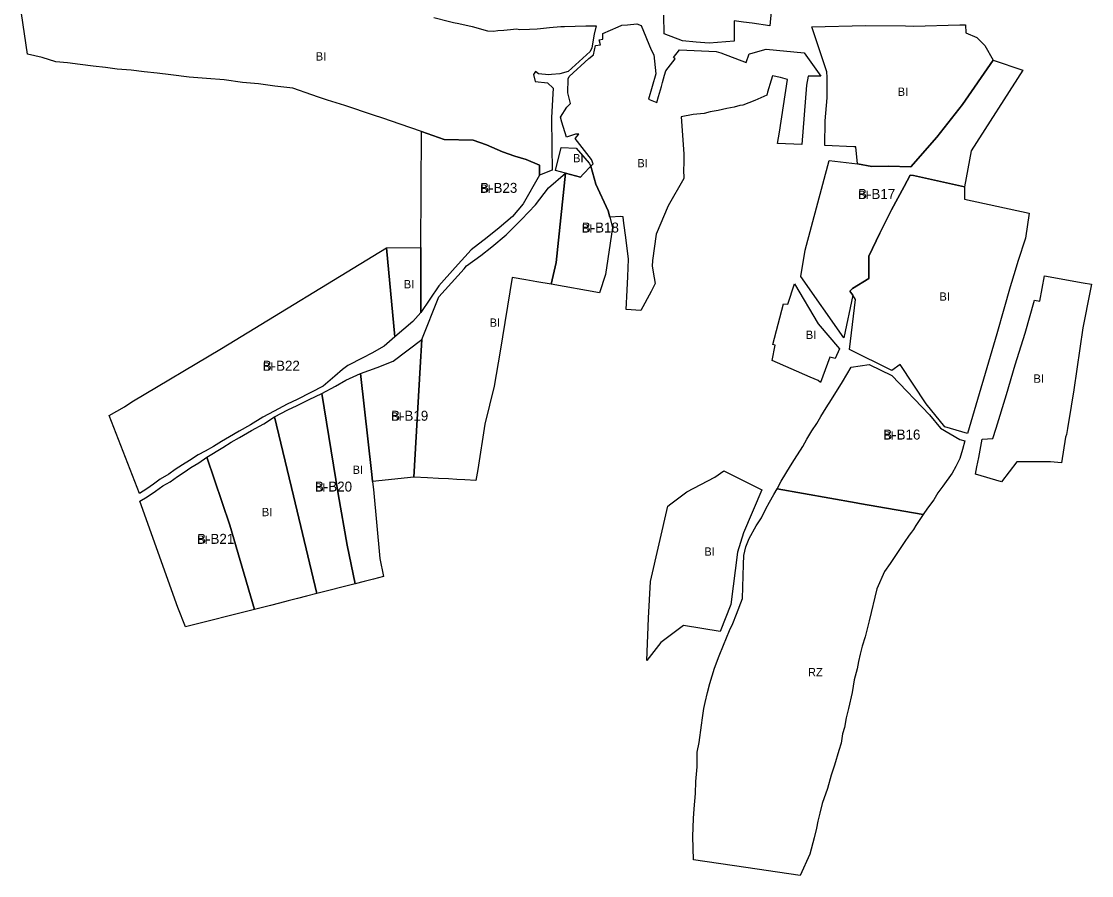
# Model space of a CAD drawing. Extents: x -532081 to -530154, y -1179372 to -1177675.
# Drawn here: x -531490 to -530847, y -1178963 to -1178449 of the extents above; entities that cross this region are included whole.
import ezdxf

# ---------------------------------------------------------------- set-up
doc = ezdxf.new("R2010")
doc.units = 0
for name, color, linetype in [('90040013', 7, 'Continuous'), ('90040023', 7, 'Continuous'), ('90100013', 7, 'Continuous'), ('ID_navrh', 7, 'Continuous')]:
    doc.layers.add(name, color=color, linetype=linetype)

msp = doc.modelspace()

# ---------------------------------------------------------------- linework, layer by layer
at = {"layer": '90040013'}
for points in [[(-531038.59, -1178437.02), (-531040.03, -1178451.99), (-531050.64, -1178450.37), (-531055.86, -1178449.83), (-531061.44, -1178449.1), (-531061.44, -1178461.19), (-531076.38, -1178462.4), (-531084.22, -1178461.79), (-531092.53, -1178461.07), (-531103.5, -1178456.96), (-531103.74, -1178445.71)], [(-531241.84, -1178446.98), (-531232.53, -1178449.47), (-531230.18, -1178450.1), (-531226.87, -1178450.69), (-531218.89, -1178452.44), (-531209.75, -1178454.98), (-531206.06, -1178455.37), (-531203.48, -1178454.81), (-531199.75, -1178454.64), (-531195.9, -1178454.24), (-531192.27, -1178453.8), (-531190.29, -1178454.35), (-531184.34, -1178454.13), (-531179.83, -1178453.91), (-531177.85, -1178453.72), (-531172.39, -1178453.06), (-531165.63, -1178452.5), (-531163.38, -1178452.4), (-531150.57, -1178452.02), (-531144.29, -1178452.15), (-531145.55, -1178457.17), (-531146.98, -1178465.31), (-531147.93, -1178467.42), (-531161.25, -1178479.55), (-531166.29, -1178480.88), (-531171.17, -1178481.25), (-531172.83, -1178481.5), (-531179.04, -1178480.9), (-531180.76, -1178479.53), (-531181.97, -1178481.41), (-531180.96, -1178485.59), (-531173.52, -1178486.27), (-531170.25, -1178489.55), (-531170.48, -1178492.94), (-531171.13, -1178507.09), (-531170.94, -1178524.81), (-531170.78, -1178538.85), (-531178.46, -1178541.91), (-531178.31, -1178535.78), (-531186.51, -1178532.36), (-531193.32, -1178530.34), (-531200.6, -1178527.7), (-531210.2, -1178523.66), (-531218.27, -1178520.75), (-531235.78, -1178520.31), (-531249.37, -1178515.57), (-531262.22, -1178511.21), (-531272.6, -1178507.61), (-531278.25, -1178505.73), (-531295.36, -1178500.01), (-531305.79, -1178496.65), (-531311.3, -1178494.88), (-531315.23, -1178493.5), (-531326.64, -1178489.55), (-531337.48, -1178488.37), (-531347.31, -1178486.98), (-531356.95, -1178486.2), (-531367.96, -1178484.62), (-531378.59, -1178483.63), (-531389.01, -1178482.84), (-531400.03, -1178481.46), (-531408.09, -1178480.47), (-531415.96, -1178479.68), (-531423.82, -1178478.7), (-531432.09, -1178478.11), (-531439.17, -1178477.12), (-531446.64, -1178476.33), (-531454.51, -1178475.34), (-531461.98, -1178474.36), (-531469.06, -1178473.77), (-531477.33, -1178471.2), (-531486.01, -1178469.03), (-531489.73, -1178444.75)]]:
    msp.add_lwpolyline(points, dxfattribs=at)
for points in [[(-531147.65, -1178536.43), (-531146.23, -1178534.97), (-531147.19, -1178532.46), (-531156.94, -1178519.71), (-531154.83, -1178517.16), (-531156.76, -1178517.26), (-531162.17, -1178518.99), (-531165.08, -1178509.9), (-531165.86, -1178506.92), (-531161.98, -1178500.97), (-531159.76, -1178498.66), (-531161.34, -1178492.33), (-531161.12, -1178483.96), (-531160.67, -1178482.6), (-531148.72, -1178471.75), (-531146.01, -1178469.49), (-531144.66, -1178463.84), (-531141.79, -1178463.58), (-531142.5, -1178460.54), (-531140.31, -1178460.04), (-531140.38, -1178456.6), (-531131.13, -1178452.75), (-531128.88, -1178451.62), (-531125.5, -1178451.4), (-531119.86, -1178450.95), (-531117.38, -1178451.85), (-531111.3, -1178466.55), (-531109.78, -1178469.48), (-531108.48, -1178480.88), (-531112.99, -1178496.17), (-531107.96, -1178498.18), (-531106.89, -1178494.51), (-531105.15, -1178488.56), (-531104.53, -1178486.14), (-531103.35, -1178481.73), (-531102.59, -1178479.09), (-531096.89, -1178471.98), (-531097.93, -1178471.15), (-531094.21, -1178466.52), (-531072.17, -1178467.44), (-531069.49, -1178468.26), (-531054.18, -1178474.07), (-531052.38, -1178468.88), (-531051.45, -1178468.62), (-531042.3, -1178466.11), (-531019.42, -1178468.38), (-531009.35, -1178482.35), (-531016.9, -1178482.35), (-531017.93, -1178487.67), (-531020.87, -1178523.48), (-531035.3, -1178522.85), (-531034.28, -1178516.02), (-531029.48, -1178484.28), (-531033.57, -1178483.21), (-531038.37, -1178482.14), (-531039.26, -1178484.64), (-531041.39, -1178491.95), (-531041.75, -1178493.73), (-531049.11, -1178497), (-531056.22, -1178499.75), (-531058.03, -1178499.97), (-531061.42, -1178500.88), (-531065.94, -1178501.79), (-531071.14, -1178502.92), (-531075.89, -1178503.83), (-531079.51, -1178504.74), (-531086.1, -1178505.3), (-531093.28, -1178506.82), (-531091.61, -1178529.05), (-531091.65, -1178534.79), (-531091.86, -1178538.38), (-531091.72, -1178543.75), (-531101, -1178560.31), (-531108.31, -1178577.24), (-531110.57, -1178593.08), (-531110.69, -1178596.42), (-531109.5, -1178603.44), (-531108.91, -1178606.9), (-531111.4, -1178611.78), (-531117.46, -1178623.21), (-531126.26, -1178622.6), (-531125.77, -1178610.94), (-531125.29, -1178602.61), (-531124.94, -1178592.25), (-531126.39, -1178580.96), (-531128, -1178569.06), (-531128.14, -1178566.76), (-531129.57, -1178566.64), (-531136.08, -1178567.01), (-531137.19, -1178563.31), (-531144.46, -1178547.24)], [(-530922.36, -1178451.42), (-530922.24, -1178456.29), (-530915.72, -1178459.01), (-530910.89, -1178463.79), (-530905.76, -1178472.63), (-530924.32, -1178499.4), (-530939.6, -1178518.98), (-530955.29, -1178536.9), (-530968.7, -1178536.38), (-530978.65, -1178536.57), (-530987.3, -1178534.98), (-530988.4, -1178524.84), (-530989.44, -1178524.84), (-531006.92, -1178524.08), (-531006.76, -1178509.16), (-531005.65, -1178495.35), (-531005.49, -1178482.97), (-531005.81, -1178479.79), (-531013.6, -1178456.32), (-531014.8, -1178452.7), (-530982.48, -1178451.8), (-530958.48, -1178452.03), (-530953.63, -1178452.19), (-530925.9, -1178451.51)], [(-531147.65, -1178536.43), (-531152.22, -1178541.12), (-531153.85, -1178542.92), (-531162.87, -1178540.69), (-531168.71, -1178539.1), (-531165.45, -1178525.23), (-531156.32, -1178525.58), (-531148.57, -1178534.56)], [(-531162.87, -1178540.69), (-531168.4, -1178594.27), (-531171.41, -1178607.36), (-531179.93, -1178605.87), (-531186.56, -1178604.71), (-531194.79, -1178603.27), (-531201.96, -1178647.61), (-531205.61, -1178668.57), (-531211.19, -1178691.48), (-531215.41, -1178718.6), (-531216.62, -1178725.33), (-531223.2, -1178724.95), (-531228.01, -1178724.68), (-531233.15, -1178724.39), (-531239.08, -1178724.05), (-531245.8, -1178723.67), (-531253.89, -1178723.21), (-531250.15, -1178657.42), (-531249.19, -1178640.53), (-531238.8, -1178614.88), (-531223.64, -1178598.1), (-531222.18, -1178596.27), (-531213.65, -1178590.04), (-531207.08, -1178584.91), (-531198.43, -1178577.58), (-531189.17, -1178568.54), (-531180.77, -1178559.74), (-531172.98, -1178549.48)], [(-530903.62, -1178637.17), (-530921.15, -1178697.01), (-530934.83, -1178693.04), (-530946.16, -1178679.14), (-530961.63, -1178655.5), (-530966.67, -1178659.29), (-530992.04, -1178646.66), (-530988.44, -1178616.52), (-530990.22, -1178613.95), (-530991.89, -1178611.53), (-530990.36, -1178610), (-530980.53, -1178603.86), (-530980.53, -1178590.49), (-530973.97, -1178576.69), (-530966.98, -1178562.66), (-530959.33, -1178548.63), (-530955.62, -1178541.84), (-530953.65, -1178542.06), (-530923.06, -1178548.85), (-530923.06, -1178556.3), (-530884.17, -1178564.63), (-530886.36, -1178579.75), (-530890.95, -1178593.78), (-530892.57, -1178599.13), (-530895.53, -1178608.9), (-530899.47, -1178622.27)], [(-531254.57, -1178629.67), (-531265.42, -1178638.9), (-531270.28, -1178585.45), (-531249.65, -1178585.37), (-531249.81, -1178624.39)], [(-530847.45, -1178611.31), (-530851.93, -1178633.6), (-530857.36, -1178670.82), (-530858.98, -1178680.59), (-530861.22, -1178694.07), (-530861.82, -1178697.62), (-530862.27, -1178699.3), (-530864.65, -1178714.67), (-530871.39, -1178714.02), (-530891.58, -1178714.02), (-530900.79, -1178726.01), (-530916.47, -1178721.44), (-530915.6, -1178717.02), (-530914.51, -1178711.45), (-530912.36, -1178700.52), (-530905.95, -1178699.97), (-530904.06, -1178693.87), (-530897.78, -1178673.68), (-530892.49, -1178655.71), (-530886.59, -1178636.78), (-530880.93, -1178616.84), (-530877.85, -1178617.45), (-530874.9, -1178602.31), (-530851.63, -1178606.49), (-530846.66, -1178607.39)], [(-531025.14, -1178607.14), (-531010.93, -1178631.14), (-530998.16, -1178646.12), (-531000.68, -1178651.89), (-531003.91, -1178651.17), (-531009.49, -1178666.33), (-531010.9, -1178665.28), (-531015.7, -1178663.11), (-531038.64, -1178653.15), (-531036.84, -1178643.95), (-531038.28, -1178643.59), (-531031.8, -1178619.23), (-531029.1, -1178619.41)], [(-531283.71, -1178786.01), (-531289.09, -1178787.37), (-531293.9, -1178764.23), (-531299.3, -1178733.22), (-531309.26, -1178673), (-531300.96, -1178668.53), (-531294.88, -1178664.96), (-531285.94, -1178660.96), (-531279.19, -1178721.77), (-531278.72, -1178725.97), (-531278.35, -1178729.31), (-531278.19, -1178730.75), (-531274.27, -1178772.11), (-531272.15, -1178783.07), (-531278.06, -1178784.57)], [(-531340.07, -1178800.34), (-531349.62, -1178802.77), (-531364.57, -1178752.17), (-531378.23, -1178711.23), (-531368.59, -1178705.43), (-531363.69, -1178702.3), (-531358.65, -1178699.48), (-531351.53, -1178695.16), (-531343.97, -1178691.15), (-531337.59, -1178687.13), (-531326.29, -1178734.45), (-531312.3, -1178793.28), (-531318.39, -1178794.83), (-531323.86, -1178796.22), (-531329.37, -1178797.62), (-531334.63, -1178798.96)], [(-531063.52, -1178799.91), (-531069.76, -1178816.05), (-531091.95, -1178812.38), (-531105.52, -1178822.64), (-531113.89, -1178833.52), (-531112.99, -1178807.99), (-531111.8, -1178786.05), (-531101.21, -1178740.77), (-531099.47, -1178739.37), (-531089.95, -1178732.07), (-531073.08, -1178723.27), (-531067.67, -1178719.52), (-531044.85, -1178730.85), (-531055.85, -1178756.7), (-531059.52, -1178768.34)]]:
    msp.add_lwpolyline(points, close=True, dxfattribs=at)
at = {"layer": '90040023'}
for points in [[(-530923.06, -1178548.85), (-530953.65, -1178542.06), (-530955.62, -1178541.84), (-530959.33, -1178548.63), (-530966.98, -1178562.66), (-530973.97, -1178576.69), (-530980.53, -1178590.49), (-530980.53, -1178603.86), (-530990.36, -1178610), (-530991.89, -1178611.53), (-530990.22, -1178613.95), (-530995.62, -1178639.62), (-531021.29, -1178602.76), (-531018.78, -1178586.88), (-531004.28, -1178532.99), (-530987.3, -1178534.98), (-530978.65, -1178536.57), (-530968.7, -1178536.38), (-530955.29, -1178536.9), (-530939.6, -1178518.98), (-530924.32, -1178499.4), (-530905.76, -1178472.63), (-530888.03, -1178478.75), (-530919.11, -1178527.18)], [(-531249.65, -1178585.37), (-531249.37, -1178515.57), (-531235.78, -1178520.31), (-531218.27, -1178520.75), (-531210.2, -1178523.66), (-531200.6, -1178527.7), (-531193.32, -1178530.34), (-531186.51, -1178532.36), (-531178.31, -1178535.78), (-531178.46, -1178541.91), (-531188.2, -1178559.01), (-531194.65, -1178566.58), (-531202.57, -1178573.55), (-531209.88, -1178579.29), (-531219.38, -1178586.77), (-531229.13, -1178597.22), (-531238.88, -1178608.34), (-531249.81, -1178624.39)], [(-531168.4, -1178594.27), (-531162.87, -1178540.69), (-531153.85, -1178542.92), (-531152.22, -1178541.12), (-531147.65, -1178536.43), (-531144.46, -1178547.24), (-531137.19, -1178563.31), (-531136.08, -1178567.01), (-531134.6, -1178573.31), (-531138.67, -1178601.49), (-531142.43, -1178612.44), (-531171.41, -1178607.36)], [(-531437.02, -1178686.21), (-531427.79, -1178681.11), (-531423.31, -1178678.05), (-531369.55, -1178646.03), (-531270.28, -1178585.45), (-531265.42, -1178638.9), (-531271.67, -1178644.51), (-531279.23, -1178648.79), (-531284.65, -1178651.59), (-531293.53, -1178656.21), (-531296.81, -1178658.68), (-531301.42, -1178662.64), (-531308.44, -1178668.53), (-531315.87, -1178672.48), (-531323.98, -1178676.66), (-531330.06, -1178679.48), (-531337.93, -1178683.66), (-531344.69, -1178687.27), (-531352, -1178691.78), (-531358.87, -1178695.62), (-531364.61, -1178699.01), (-531369.51, -1178701.85), (-531374.3, -1178704.82), (-531379.22, -1178707.64), (-531383.44, -1178709.9), (-531388.65, -1178713.28), (-531393.01, -1178715.96), (-531397.37, -1178718.64), (-531401.16, -1178721.47), (-531406.37, -1178724.43), (-531410.45, -1178727.53), (-531414.39, -1178730.36), (-531418.75, -1178733.18)], [(-531253.89, -1178723.21), (-531278.72, -1178725.97), (-531279.19, -1178721.77), (-531285.94, -1178660.96), (-531275.96, -1178657.36), (-531266.37, -1178653.55), (-531249.19, -1178640.53), (-531250.15, -1178657.42)], [(-530988.05, -1178738.71), (-531035.66, -1178730.29), (-531033.11, -1178725.68), (-531030.47, -1178721.06), (-531027.63, -1178716.45), (-531025.13, -1178712.69), (-531020.21, -1178704.79), (-531017.85, -1178700.45), (-531014.7, -1178695.52), (-531011.75, -1178690.98), (-531009.39, -1178686.83), (-531006.14, -1178681.7), (-531002.9, -1178676.57), (-530996.32, -1178665.91), (-530991.21, -1178657.23), (-530980.39, -1178655.65), (-530966.61, -1178662.16), (-530943.99, -1178685.84), (-530937.49, -1178693.94), (-530925.88, -1178700.65), (-530922.86, -1178701.47), (-530924.3, -1178706.59), (-530925.89, -1178712.02), (-530928.28, -1178716.98), (-530930.51, -1178720.98), (-530936.13, -1178728.8), (-530938.97, -1178732.79), (-530941.53, -1178736.92), (-530945.22, -1178741.9), (-530947.92, -1178745.75), (-530986.1, -1178739.05)], [(-531312.3, -1178793.28), (-531326.29, -1178734.45), (-531337.59, -1178687.13), (-531329.73, -1178682.81), (-531324.1, -1178680.14), (-531316.83, -1178676.72), (-531309.26, -1178673), (-531299.3, -1178733.22), (-531293.9, -1178764.23), (-531289.09, -1178787.37)], [(-531395.73, -1178801.65), (-531418.64, -1178737.77), (-531414.06, -1178735.09), (-531409.1, -1178731.64), (-531404.71, -1178728.58), (-531400.32, -1178726.09), (-531395.93, -1178722.83), (-531391.92, -1178720.35), (-531387.91, -1178717.47), (-531383.14, -1178714.6), (-531378.23, -1178711.23), (-531364.57, -1178752.17), (-531349.62, -1178802.77), (-531391.16, -1178813.33)]]:
    msp.add_lwpolyline(points, close=True, dxfattribs=at)
at = {"layer": '90100013'}
msp.add_lwpolyline([(-531085.02, -1178917.99), (-531084.62, -1178913.33), (-531084.45, -1178906.18), (-531083.75, -1178897.46), (-531083.58, -1178888.57), (-531082.4, -1178882.8), (-531081, -1178872.25), (-531080.44, -1178867.9), (-531079.6, -1178862.41), (-531078.9, -1178858.76), (-531077.48, -1178852.78), (-531076.04, -1178847.33), (-531073.32, -1178838.03), (-531070.5, -1178830.75), (-531067.88, -1178824.35), (-531066.06, -1178819.77), (-531064.23, -1178815.45), (-531062.27, -1178811.25), (-531060.05, -1178805.62), (-531056.39, -1178796.19), (-531055.87, -1178775.77), (-531055.61, -1178770.4), (-531054.35, -1178765.15), (-531052.4, -1178760.14), (-531048.19, -1178752.58), (-531045.05, -1178747.67), (-531042.31, -1178742.37), (-531040.26, -1178738.25), (-531037.61, -1178733.63), (-531035.66, -1178730.29), (-530988.05, -1178738.71), (-530986.1, -1178739.05), (-530947.92, -1178745.75), (-530950.75, -1178749.88), (-530952.25, -1178752.26), (-530953.75, -1178754.65), (-530954.98, -1178756.41), (-530956.21, -1178758.17), (-530959.26, -1178762.52), (-530962.54, -1178767.34), (-530967.68, -1178775.28), (-530971.01, -1178779.99), (-530975.71, -1178790.32), (-530980.25, -1178809.61), (-530982.82, -1178819.34), (-530984.55, -1178824.85), (-530985.68, -1178829.73), (-530986.7, -1178834.04), (-530987.61, -1178838.58), (-530989.3, -1178845.04), (-530990.51, -1178852.78), (-530992.75, -1178862.4), (-530994.19, -1178867.86), (-530995.08, -1178873.66), (-530996.34, -1178877.46), (-530997.18, -1178883.08), (-530998.58, -1178887.58), (-531001.24, -1178896.3), (-531003.09, -1178902.34), (-531005.35, -1178910.36), (-531008.65, -1178919.43), (-531010.04, -1178925.19), (-531011.24, -1178930.01), (-531012.03, -1178934.27), (-531013.45, -1178939.97), (-531015.97, -1178949.93), (-531021.8, -1178962.74), (-531028.52, -1178961.73), (-531054.44, -1178957.84), (-531085.97, -1178953.25), (-531086.28, -1178939.33), (-531085.81, -1178928.42), (-531085.49, -1178922.57)], close=True, dxfattribs=at)

# ---------------------------------------------------------------- texts
at = {"layer": '90040013'}
for rotation, p in [(0, (-531312.86, -1178472.94)), (360, (-530963.16, -1178494.16)), (0, (-531158.26, -1178534.08)), (0, (-531119.62, -1178537.08)), (0, (-531259.97, -1178609.83)), (360, (-530938.11, -1178617.26)), (0, (-531208.38, -1178632.93)), (360, (-531018.4, -1178640.23)), (360, (-531290.71, -1178721.34)), (360, (-531345.26, -1178746.75)), (0, (-531079.37, -1178770.5))]:
    msp.add_text('BI', height=5, rotation=rotation, dxfattribs=at).set_placement(p)
msp.add_text('BI', height=5, dxfattribs=at).set_placement((-530881.57, -1178666.56))
at = {"layer": '90040023'}
for rotation, p in [(0, (-531214.06, -1178552.43)), (0, (-530986.96, -1178556.12)), (0, (-531153.01, -1178576.29)), (360, (-531344.71, -1178659.31)), (0, (-531267.56, -1178689.38)), (0, (-530971.84, -1178700.7)), (0, (-531313.34, -1178731.96)), (360, (-531384.13, -1178763.37))]:
    msp.add_text('BI', height=5, rotation=rotation, dxfattribs=at).set_placement(p)
at = {"layer": '90100013'}
msp.add_text('RZ', height=5, rotation=0, dxfattribs=at).set_placement((-531017.1, -1178842.99))
at = {"layer": 'ID_navrh'}
for s, rotation, p in [('B-B23', 360, (-531214.06, -1178552.43)), ('B-B17', 0, (-530986.96, -1178556.12)), ('B-B18', 360, (-531153.01, -1178576.29)), ('B-B22', 360, (-531344.71, -1178659.31)), ('B-B19', 0, (-531267.56, -1178689.38)), ('B-B16', 360, (-530971.84, -1178700.7)), ('B-B20', 0, (-531313.34, -1178731.96)), ('B-B21', 0, (-531384.13, -1178763.37))]:
    msp.add_text(s, height=6, rotation=rotation, dxfattribs=at).set_placement(p)

doc.saveas('drawing.dxf')
